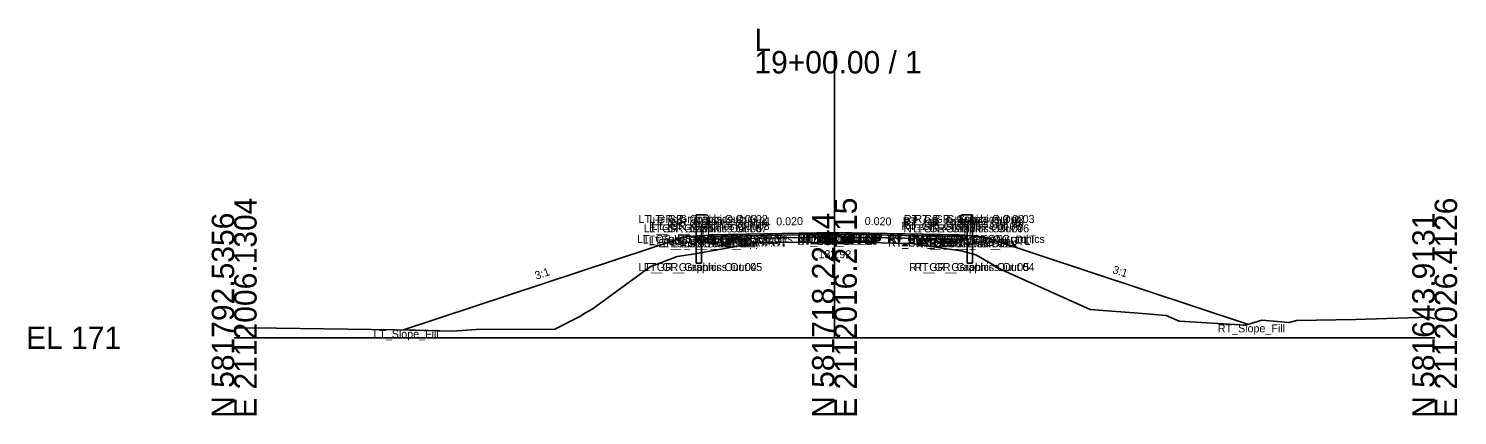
# Model space of a CAD drawing. Extents: x -486 to 1153, y -333 to 9539.
# Drawn here: x -25.7 to 152.8, y 9490.3 to 9538.6 of the extents above; entities that cross this region are included whole.
import ezdxf

# ---------------------------------------------------------------- set-up
doc = ezdxf.new("R2010")
doc.units = 0
for name, color, linetype in [('Default', 7, 'Continuous'), ('Exist Cross Section Cell', 7, 'Continuous'), ('Exist XS Ground Line', 7, 'Continuous'), ('Prop CMT Guardrail Graphics', 7, 'Continuous'), ('Prop CMT Pvmt Course 1', 7, 'Continuous'), ('Prop CMT Pvmt Course 2', 7, 'Continuous'), ('Prop CMT Pvmt Course 3', 7, 'Continuous'), ('Prop CMT Pvmt Surface', 7, 'Continuous'), ('Prop CMT Pvmt Surface Shoulder', 7, 'Continuous'), ('Prop CMT Shld Paved Course 1', 7, 'Continuous'), ('Prop CMT Shld Paved Course 2', 7, 'Continuous'), ('Prop CMT Shld Paved Course 3', 7, 'Continuous'), ('Prop CMT Slope Grass', 7, 'Continuous'), ('Prop CMT Subgrade Earthwork', 7, 'Continuous'), ('Prop XS Earthwork Shape', 7, 'Continuous'), ('Prop XS SE Text', 7, 'Continuous'), ('Prop XS Side Slope Text', 7, 'Continuous'), ('Scratch_Level_0', 7, 'Continuous')]:
    doc.layers.add(name, color=color, linetype=linetype)

msp = doc.modelspace()

# ---------------------------------------------------------------- linework, layer by layer
at = {"layer": 'Exist Cross Section Cell'}
for p, q in [((75, 9500), (75, 9535.78)), ((0, 9500), (75, 9500)), ((75, 9500), (150, 9500))]:
    msp.add_line(p, q, dxfattribs=at)
at = {"layer": 'Exist XS Ground Line'}
for p, q in [((55.35, 9510.12), (57.55, 9510.48)), ((57.55, 9510.48), (65.29, 9511.86)), ((65.29, 9511.86), (67.67, 9511.88)), ((67.67, 9511.88), (74.62, 9511.93)), ((74.62, 9511.93), (75, 9511.92)), ((75, 9511.92), (77.19, 9511.91)), ((77.19, 9511.91), (84.63, 9511.74)), ((84.63, 9511.74), (88.76, 9511.15)), ((88.76, 9511.15), (90.85, 9510.85)), ((90.85, 9510.85), (92.66, 9510.34)), ((44.71, 9503.57), (51.96, 9508.84)), ((51.96, 9508.84), (55.35, 9510.12)), ((92.66, 9510.34), (95.93, 9508.47)), ((95.93, 9508.47), (106.94, 9503.51)), ((43.89, 9503.11), (44.71, 9503.57)), ((106.94, 9503.51), (113.48, 9503.04)), ((40.07, 9501.07), (43.2, 9502.64)), ((43.2, 9502.64), (43.89, 9503.11)), ((113.48, 9503.04), (116.45, 9502.76)), ((116.45, 9502.76), (118.09, 9502.06)), ((118.09, 9502.06), (126.36, 9501.56)), ((126.36, 9501.56), (128.39, 9502.21)), ((128.39, 9502.21), (131.81, 9501.88)), ((131.81, 9501.88), (132.77, 9502.17)), ((132.77, 9502.17), (140.09, 9502.26)), ((140.09, 9502.26), (149.25, 9502.57)), ((149.25, 9502.57), (150, 9502.37)), ((0, 9501.2), (0.37, 9501.19)), ((0.37, 9501.19), (2.31, 9501.24)), ((2.31, 9501.24), (20.13, 9500.99)), ((20.13, 9500.99), (27.23, 9500.8)), ((27.23, 9500.8), (30.22, 9501.04)), ((30.22, 9501.04), (40.07, 9501.07))]:
    msp.add_line(p, q, dxfattribs=at)
at = {"layer": 'Prop CMT Guardrail Graphics'}
for points in [[(57.73, 9509.32), (57.73, 9515.32)], [(57.73, 9515.32), (59.07, 9515.32), (59.34, 9515.03)], [(59.34, 9514.45), (59.07, 9514.15), (58.4, 9514.15)], [(58.4, 9514.15), (58.4, 9509.32)], [(59.34, 9515.03), (59.07, 9514.74)], [(59.07, 9514.74), (59.34, 9514.45)], [(92.27, 9515.32), (90.93, 9515.32), (90.66, 9515.03)], [(90.66, 9515.03), (90.93, 9514.74)], [(90.93, 9514.74), (90.66, 9514.45)], [(90.66, 9514.45), (90.93, 9514.15), (91.6, 9514.15)], [(91.6, 9514.15), (91.6, 9509.32)], [(92.27, 9509.32), (92.27, 9515.32)], [(58.4, 9509.32), (57.73, 9509.32)], [(91.6, 9509.32), (92.27, 9509.32)]]:
    msp.add_lwpolyline(points, dxfattribs=at)
at = {"layer": 'Prop CMT Pvmt Course 1'}
for points in [[(75, 9513.14), (64, 9512.92)], [(64, 9512.71), (75, 9512.93)], [(64, 9512.92), (64, 9512.71)], [(75, 9512.93), (75, 9513.14)], [(75, 9513.14), (86, 9512.92)], [(75, 9512.93), (75, 9513.14)], [(86, 9512.71), (75, 9512.93)], [(86, 9512.92), (86, 9512.71)]]:
    msp.add_lwpolyline(points, dxfattribs=at)
msp.add_lwpolyline([(75, 9512.93), (75, 9513.02), (75, 9513.02), (75, 9512.93)], close=True, dxfattribs=at)
msp.add_lwpolyline([(75, 9512.93), (75, 9513.02), (75, 9513.02), (75, 9512.93)], close=True, dxfattribs=at)
at = {"layer": 'Prop CMT Pvmt Course 2'}
for points in [[(75, 9512.93), (64, 9512.71)], [(64, 9512.71), (64, 9512.38)], [(64, 9512.38), (75, 9512.6)], [(75, 9512.6), (75, 9512.93)], [(75, 9512.6), (75, 9512.93)], [(75, 9512.93), (86, 9512.71)], [(86, 9512.38), (75, 9512.6)], [(86, 9512.71), (86, 9512.38)]]:
    msp.add_lwpolyline(points, dxfattribs=at)
at = {"layer": 'Prop CMT Pvmt Course 3'}
for points in [[(75, 9512.6), (64, 9512.38)], [(64, 9512.38), (64, 9512.38)], [(75, 9512.6), (75, 9512.6)], [(75, 9512.6), (86, 9512.38)], [(75, 9512.6), (75, 9512.6)], [(86, 9512.38), (86, 9512.38)]]:
    msp.add_lwpolyline(points, dxfattribs=at)
at = {"layer": 'Prop CMT Pvmt Surface'}
for points in [[(75, 9513.14), (64, 9512.92)], [(75, 9513.14), (86, 9512.92)]]:
    msp.add_lwpolyline(points, dxfattribs=at)
at = {"layer": 'Prop CMT Pvmt Surface Shoulder'}
for points in [[(64, 9512.92), (59.44, 9512.83)], [(86, 9512.92), (90.56, 9512.83)]]:
    msp.add_lwpolyline(points, dxfattribs=at)
at = {"layer": 'Prop CMT Shld Paved Course 1'}
for points in [[(64, 9512.92), (59.44, 9512.83), (59.22, 9512.62)], [(59.22, 9512.62), (64, 9512.71)], [(64, 9512.71), (64, 9512.92)], [(86, 9512.92), (90.56, 9512.83), (90.78, 9512.62)], [(86, 9512.71), (86, 9512.92)], [(90.78, 9512.62), (86, 9512.71)]]:
    msp.add_lwpolyline(points, dxfattribs=at)
at = {"layer": 'Prop CMT Shld Paved Course 2'}
for points in [[(64, 9512.71), (59.22, 9512.62), (58.88, 9512.28)], [(58.88, 9512.28), (64, 9512.38)], [(64, 9512.38), (64, 9512.71)], [(86, 9512.71), (90.78, 9512.62), (91.12, 9512.28)], [(86, 9512.38), (86, 9512.71)], [(91.12, 9512.28), (86, 9512.38)]]:
    msp.add_lwpolyline(points, dxfattribs=at)
at = {"layer": 'Prop CMT Shld Paved Course 3'}
for points in [[(64, 9512.38), (58.88, 9512.28)], [(58.88, 9512.28), (58.88, 9512.28), (58.88, 9512.28)], [(64, 9512.38), (64, 9512.38)], [(86, 9512.38), (91.12, 9512.28)], [(86, 9512.38), (86, 9512.38)], [(91.12, 9512.28), (91.12, 9512.28), (91.12, 9512.28)]]:
    msp.add_lwpolyline(points, dxfattribs=at)
at = {"layer": 'Prop CMT Slope Grass'}
for points in [[(56.34, 9512.58), (21.14, 9500.97)], [(59.34, 9512.82), (56.34, 9512.58)], [(59.44, 9512.83), (59.34, 9512.82)], [(90.56, 9512.83), (90.66, 9512.82)], [(90.66, 9512.82), (93.66, 9512.58)], [(93.66, 9512.58), (126.72, 9501.67)]]:
    msp.add_lwpolyline(points, dxfattribs=at)
at = {"layer": 'Prop CMT Subgrade Earthwork'}
for points in [[(58.88, 9512.28), (58.41, 9512.75)], [(64, 9512.38), (58.88, 9512.28)], [(75, 9512.6), (64, 9512.38)], [(75, 9512.6), (86, 9512.38)], [(86, 9512.38), (91.12, 9512.28)], [(91.12, 9512.28), (91.59, 9512.75)]]:
    msp.add_lwpolyline(points, dxfattribs=at)
at = {"layer": 'Prop XS Earthwork Shape'}
msp.add_lwpolyline([(43.89, 9503.11), (44.71, 9503.57), (51.96, 9508.84), (55.35, 9510.12), (57.55, 9510.48), (65.29, 9511.86), (67.67, 9511.88), (74.62, 9511.93), (75, 9511.92), (77.19, 9511.91), (84.63, 9511.74), (88.76, 9511.15), (90.85, 9510.85), (92.66, 9510.34), (95.93, 9508.47), (106.94, 9503.51), (113.48, 9503.04), (116.45, 9502.76), (118.09, 9502.06), (126.36, 9501.56), (126.72, 9501.67), (93.66, 9512.58), (91.59, 9512.75), (91.12, 9512.28), (86, 9512.38), (75, 9512.6), (64, 9512.38), (58.88, 9512.28), (58.41, 9512.75), (56.34, 9512.58), (21.14, 9500.97), (27.23, 9500.8), (30.22, 9501.04), (40.07, 9501.07), (43.2, 9502.64)], close=True, dxfattribs=at)

# ---------------------------------------------------------------- texts
at = {"layer": 'Default'}
for s, height, p in [('182.92', 1, (73.01, 9509.92)), ('-', 0.0001, (0, 9500))]:
    msp.add_text(s, height=height, dxfattribs=at).set_placement(p)
at = {"layer": 'Exist Cross Section Cell'}
for s, p in [('L', (65, 9535.78)), ('19+00.00 / 1', (65, 9532.98)), ('EL 171', (-26, 9498.6))]:
    msp.add_text(s, height=2.8, dxfattribs=at).set_placement(p)
for s, p in [('E 2112006.1304', (2.8, 9490)), ('E 2112016.2715', (77.8, 9490)), ('E 2112026.4126', (152.8, 9490)), ('N 581792.5356', (0, 9490)), ('N 581718.2244', (75, 9490)), ('N 581643.9131', (150, 9490))]:
    msp.add_text(s, height=2.8, rotation=90, dxfattribs=at).set_placement(p)
at = {"layer": 'Prop XS SE Text'}
for rotation, p in [(1.1458, (67.73, 9514)), (358.8542, (78.77, 9514.07))]:
    msp.add_text('0.020', height=1, rotation=rotation, dxfattribs=at).set_placement(p)
at = {"layer": 'Prop XS Side Slope Text'}
for rotation, p in [(18.2629, (37.75, 9507.24)), (341.7371, (109.67, 9508.09))]:
    msp.add_text('3:1', height=1, rotation=rotation, dxfattribs=at).set_placement(p)
at = {"layer": 'Scratch_Level_0'}
for s, p in [('LT_GR_Graphics Out 03', (50.52, 9514.32)), ('LT_GR_Graphics Out 06', (51.17, 9513.15)), ('LT_GR_Graphics Out 07', (51.83, 9513.15)), ('LT_GR_Graphics Out 09', (51.84, 9513.74)), ('LT_GR_Graphics Out 02', (51.87, 9514.32)), ('LT_GR_Graphics Out 08', (52.11, 9513.45)), ('LT_GR_Graphics Out 01', (52.28, 9514.03)), ('RT_GR_Graphics Out 08', (83.37, 9513.45)), ('RT_GR_Graphics Out 01', (83.55, 9514.03)), ('RT_GR_Graphics Out 07', (83.63, 9513.15)), ('RT_GR_Graphics Out 09', (83.65, 9513.74)), ('RT_GR_Graphics Out 02', (83.68, 9514.32)), ('RT_GR_Graphics Out 06', (84.31, 9513.15)), ('RT_GR_Graphics Out 03', (84.99, 9514.32)), ('LT_GS_OS_GR_Face_Graphics', (50.33, 9511.82)), ('LT_Sub_Trench_Out_DLT', (51.06, 9511.75)), ('LT_GS_OS_CTL', (51.8, 9511.58)), ('LT_Sub_Trench_Out', (52.99, 9511.28)), ('LT_PS3_Shelf_Out', (53.54, 9511.28)), ('LT_PS3_OEOP', (54.67, 9511.28)), ('LT_PS2_OEOP', (55.01, 9511.62)), ('LT_PS1_OEOP', (55.34, 9511.83)), ('LT_PV2_OEOT', (59.75, 9511.71)), ('LT_PV3_OEOT', (59.75, 9511.38)), ('LT_Sub_OEOT', (59.77, 9511.38)), ('LT_PV1_OEOT', (59.87, 9511.92)), ('RT_PV2_OEEOP', (70.33, 9511.93)), ('RT_PV3_OEEOP', (70.33, 9511.6)), ('RT_Sub_OEEOP', (70.36, 9511.6)), ('LT_PV2_OEEOP', (70.39, 9511.93)), ('LT_PV3_OEEOP', (70.39, 9511.6)), ('LT_Sub_OEEOP', (70.42, 9511.6)), ('RT_PV1_OEEOP', (70.45, 9512.02)), ('LT_PV1_OEEOP', (70.51, 9512.02)), ('RT_PV2_IEEOP', (70.71, 9511.93)), ('LT_PV2_IEEOP', (70.77, 9511.93)), ('RT_PV1_IEEOP', (70.83, 9512.02)), ('LT_PV1_IEEOP', (70.89, 9512.02)), ('PV2_PGL', (72.35, 9511.93)), ('PV1_PGL', (72.47, 9512.14)), ('RT_GS_OS_GR_Face_Graphics', (81.6, 9511.82)), ('RT_PV2_OEOT', (81.69, 9511.71)), ('RT_PV3_OEOT', (81.69, 9511.38)), ('RT_Sub_OEOT', (81.71, 9511.38)), ('RT_PV1_OEOT', (81.81, 9511.92)), ('RT_Sub_Trench_Out_DLT', (84.18, 9511.75)), ('RT_Sub_Trench_Out', (85.17, 9511.28)), ('RT_PS3_Shelf_Out', (85.71, 9511.28)), ('RT_PS1_OEOP', (86.41, 9511.83)), ('RT_PS2_OEOP', (86.5, 9511.62)), ('RT_PS3_OEOP', (86.84, 9511.28)), ('RT_GS_OS_CTL', (89.07, 9511.58)), ('LT_GR_Graphics Out 04', (50.5, 9508.32)), ('LT_GR_Graphics Out 05', (51.18, 9508.32)), ('RT_GR_Graphics Out 05', (84.32, 9508.32)), ('RT_GR_Graphics Out 04', (84.98, 9508.32)), ('RT_Slope_Fill', (122.9, 9500.67)), ('LT_Slope_Fill', (17.38, 9499.97))]:
    msp.add_text(s, height=1, dxfattribs=at).set_placement(p)

doc.saveas('drawing.dxf')
